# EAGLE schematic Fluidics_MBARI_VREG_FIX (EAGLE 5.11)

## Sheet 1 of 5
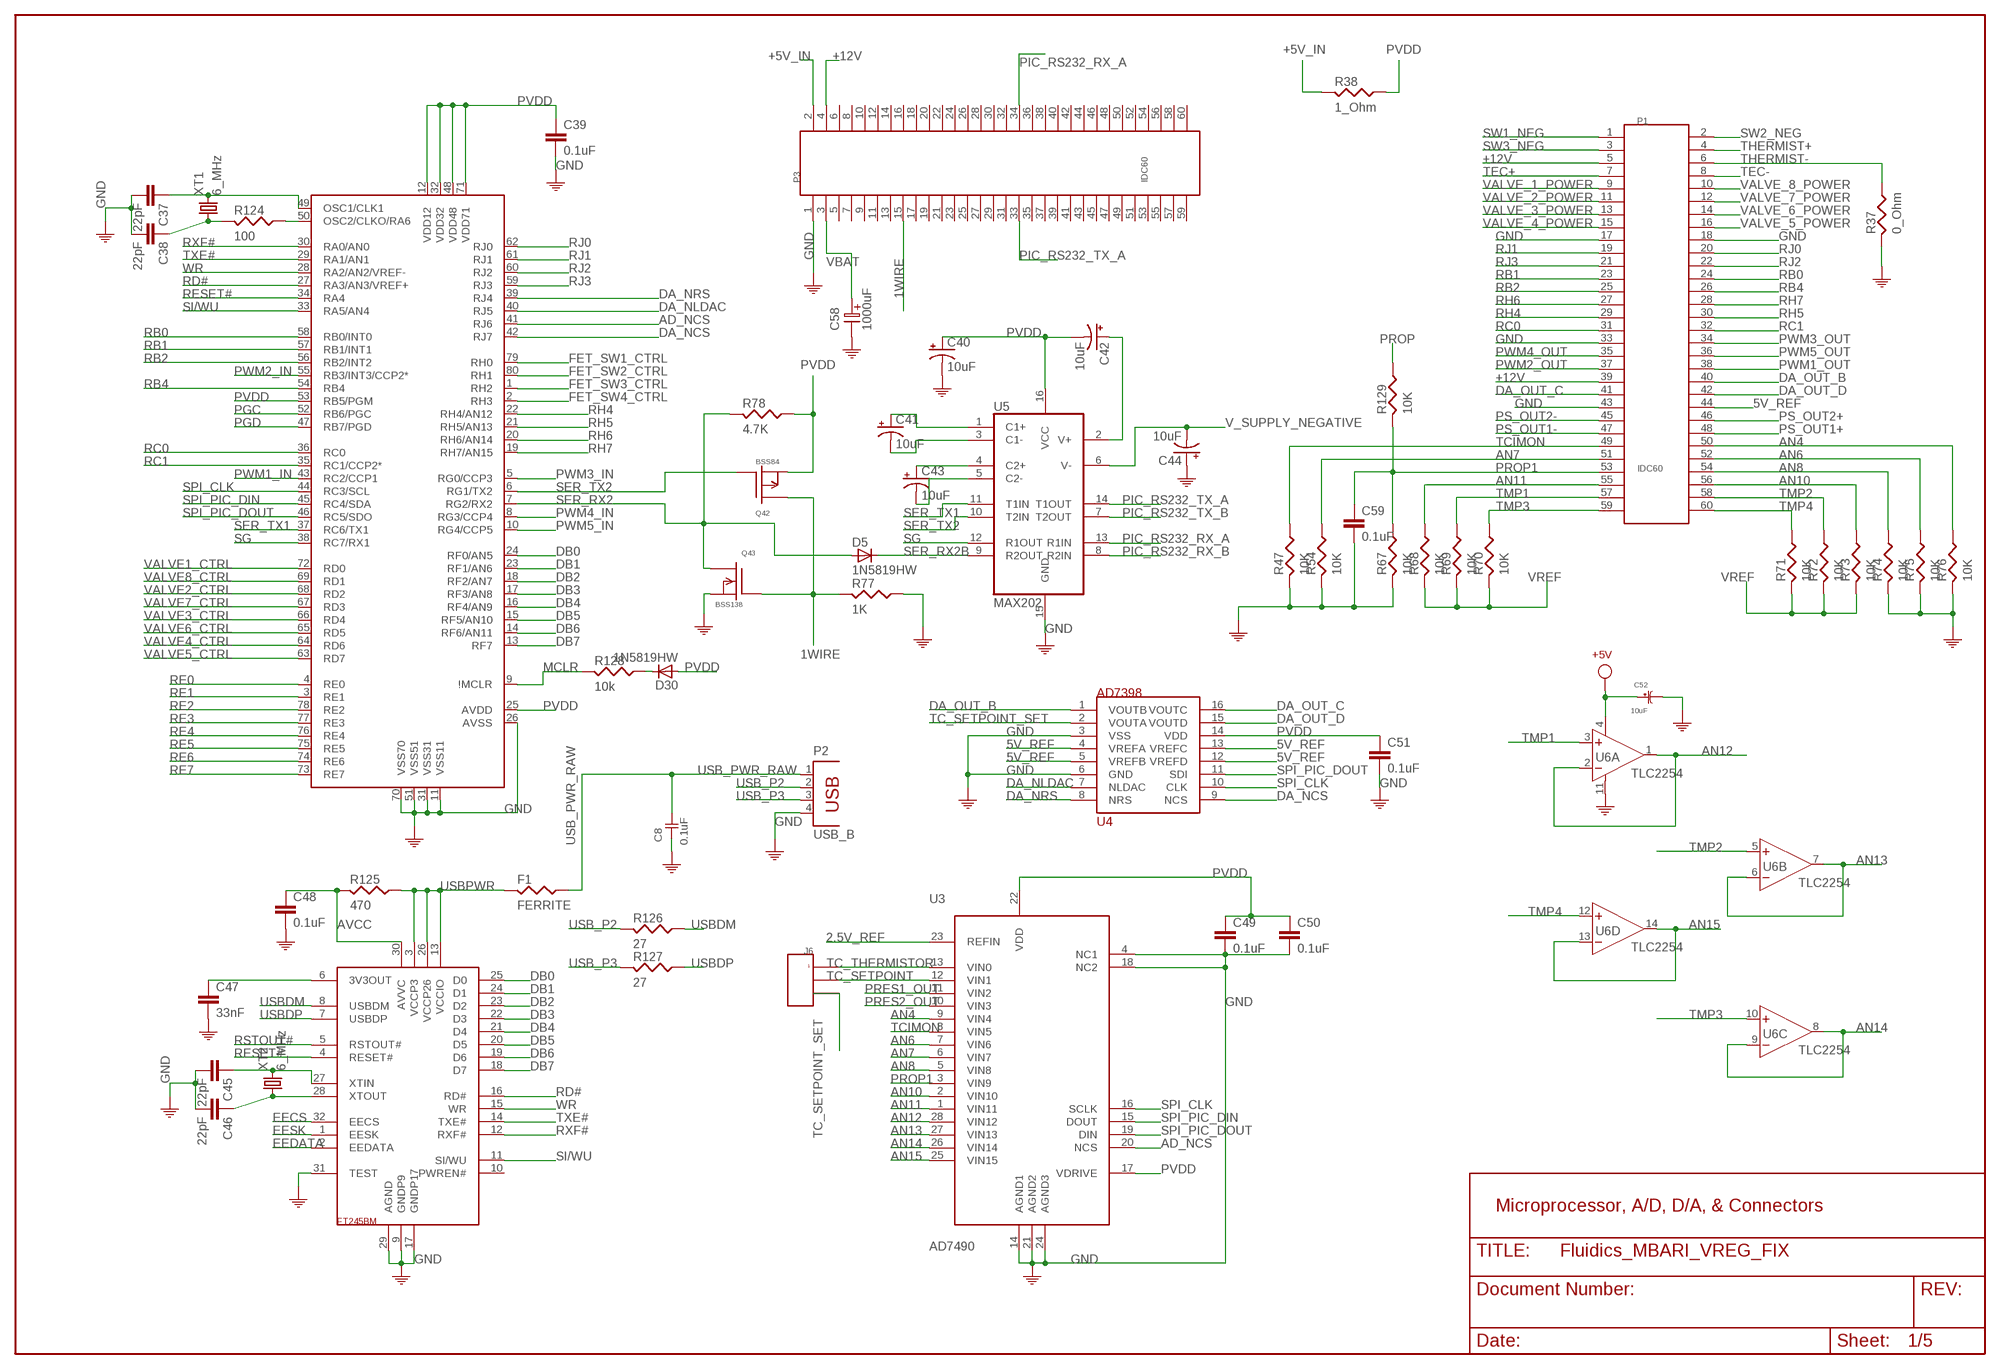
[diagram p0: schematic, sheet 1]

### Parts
C8  0.1uF  C0805  [0805]
C37  22pF  C-EUC0805  [C0805]
C38  22pF  C-EUC0805  [C0805]
C39  0.1uF  C-EUC0805  [C0805]
C40  10uF  CPOL-USCT3216  [CT3216]
C41  10uF  CPOL-USCT3216  [CT3216]
C42  10uF  CPOL-USCT3216  [CT3216]
C43  10uF  CPOL-USCT3216  [CT3216]
C44  10uF  CPOL-USCT3216  [CT3216]
C45  22pF  C-EUC0805  [C0805]
C46  22pF  C-EUC0805  [C0805]
C47  33nF  C-EUC0805  [C0805]
C48  0.1uF  C-EUC0805  [C0805]
C49  0.1uF  C-EUC0805  [C0805]
C50  0.1uF  C-EUC0805  [C0805]
C51  0.1uF  C-EUC0805  [C0805]
C52  10uF  POLCAP1210  [POLCAP1210]
C58  1000uF  ELC-5  [ES-5]
C59  0.1uF  C-EUC0805  [C0805]
D5  1N5819HW  D-SOD123  [SOD123]
D30  1N5819HW  D-SOD123  [SOD123]
F1  FERRITE  R0805  [0805]
J6  IDC3  [IDC3]
P1  IDC60  [IDC60]
P2  USB_B  PN61729  [PN61729]
P3  IDC60  [IDC60]
Q42  BSS84  MOSFETP  [SOT23]
Q43  BSS138  MOSFETN  [SOT23]
R37  0_Ohm  R0805  [0805]
R38  1_Ohm  R0805  [0805]
R47  10K  R0805  [0805]
R54  10K  R0805  [0805]
R67  10K  R0805  [0805]
R68  10K  R0805  [0805]
R69  10K  R0805  [0805]
R70  10K  R0805  [0805]
R71  10K  R0805  [0805]
R72  10K  R0805  [0805]
R73  10K  R0805  [0805]
R74  10K  R0805  [0805]
R75  10K  R0805  [0805]
R76  10K  R0805  [0805]
R77  1K  R0805  [0805]
R78  4.7K  R0805  [0805]
R124  100  R0805  [0805]
R125  470  R0805  [0805]
R126  27  R0805  [0805]
R127  27  R0805  [0805]
R128  10k  R0805  [0805]
R129  10K  R0805  [0805]
U1  PIC18F8720  PIC18F8720V1  [TQFP80]
U2  FT245BM  [LQFP-32]
U3  AD7490  [TSSOP28]
U4  AD7398  [TSSOP16]
U5  MAX202  [SO16]
U6  TLC2254  QUADOP  [SO-14]
XT1  6_MHz  CRYTALHC49S  [HC49/S]
XT2  6_MHz  CRYTALHC49S  [HC49/S]

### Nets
1WIRE: P3.15 Q42.3(D) Q43.1(G) R77.2
2.5V_REF: U3.23(REFIN) ; also sheet 4
5V_REF [+5V]: P1.44 U4.4(VREFA) U4.5(VREFB) U4.12(VREFD) U4.13(VREFC) ; also sheet 4
+5V: C52.2(+) U6.4(A:V+) ; also sheet 2,3
+5V_IN: P3.2 R38.2 ; also sheet 2,3,5
+12V: P1.5 P1.39 P3.4 ; also sheet 2,3,4,5
AD_NCS: U1.41(RJ6) U3.20(NCS)
AN4: P1.50 R76.1 U3.9(VIN4) ; also sheet 3
AN6: P1.52 R75.1 U3.7(VIN6)
AN7: P1.51 R54.1 U3.6(VIN7)
AN8: P1.54 R74.1 U3.5(VIN8) ; also sheet 3
AN10: P1.56 R73.1 U3.2(VIN10) ; also sheet 2
AN11: P1.55 R68.1 U3.1(VIN11) ; also sheet 2
AN12: U3.28(VIN12) U6.1(A:OUT) U6.2(A:-IN)
AN13: U3.27(VIN13) U6.6(B:-IN) U6.7(B:OUT)
AN14: U3.26(VIN14) U6.8(C:OUT) U6.9(C:-IN)
AN15: U3.25(VIN15) U6.13(D:-IN) U6.14(D:OUT)
AVCC: C48.1 R125.2 U2.30(AVVC)
DA_NCS: U1.42(RJ7) U4.9(NCS)
DA_NLDAC: U1.40(RJ5) U4.7(NLDAC)
DA_NRS: U1.39(RJ4) U4.8(NRS)
DA_OUT_B: P1.40 U4.1(VOUTB)
DA_OUT_C: P1.41 U4.16(VOUTC)
DA_OUT_D: P1.42 U4.15(VOUTD)
DB0: U1.24(RF0/AN5) U2.25(D0)
DB1: U1.23(RF1/AN6) U2.24(D1)
DB2: U1.18(RF2/AN7) U2.23(D2)
DB3: U1.17(RF3/AN8) U2.22(D3)
DB4: U1.16(RF4/AN9) U2.21(D4)
DB5: U1.15(RF5/AN10) U2.20(D5)
DB6: U1.14(RF6/AN11) U2.19(D6)
DB7: U1.13(RF7) U2.18(D7)
EECS: U2.32(EECS) ; also sheet 4
EEDATA: U2.2(EEDATA) ; also sheet 4
EESK: U2.1(EESK) ; also sheet 4
FET_SW1_CTRL: U1.79(RH0) ; also sheet 4
FET_SW2_CTRL: U1.80(RH1) ; also sheet 4
FET_SW3_CTRL: U1.1(RH2) ; also sheet 4
FET_SW4_CTRL: U1.2(RH3)
GND: C8.1 C37.2 C38.2 C39.2 C40.- C44.+ C45.2 C46.2 C47.2 C48.2 C49.2 C50.2 C51.2 C52.1(-) C58.2 C59.2 P1.17 P1.18 P1.33 P1.43 P2.4 P3.1 Q43.2(S) R37.2 R47.2 R54.2 R67.2 R74.2 R75.2 R76.2 R77.1 U1.11(VSS11) U1.26(AVSS) U1.31(VSS31) U1.51(VSS51) U1.70(VSS70) U2.9(GNDP9) U2.17(GNDP17) U2.29(AGND) U2.31(TEST) U3.4(NC1) U3.14(AGND1) U3.18(NC2) U3.21(AGND2) U3.24(AGND3) U4.3(VSS) U4.6(GND) U5.15(GND) U6.11(A:V-) ; also sheet 2,3,4,5
MCLR: R128.2 U1.9(\!MCLR) ; also sheet 4
N$1B: C37.1 U1.49(OSC1/CLK1) XT1.2
N$2B: C38.1 R124.2 XT1.1
N$3: R124.1 U1.50(OSC2/CLKO/RA6)
N$4B: C45.1 U2.27(XTIN) XT2.2
N$5B: C46.1 U2.28(XTOUT) XT2.1
N$92: D30.1(C) R128.1
N$93B: C47.1 U2.6(3V3OUT)
N$99B: C42.+ U5.2(V+)
N$101B: C41.+ U5.1(C1+)
N$102B: C41.- U5.3(C1-)
N$103B: C43.+ U5.4(C2+)
N$104B: C43.- U5.5(C2-)
PGC: U1.52(RB6/PGC) ; also sheet 4
PGD: U1.47(RB7/PGD) ; also sheet 4
PIC_RS232_RX_A: P3.34 U5.13(R1IN) ; also sheet 4
PIC_RS232_RX_B: U5.8(R2IN) ; also sheet 4
PIC_RS232_TX_A: P3.33 U5.14(T1OUT) ; also sheet 4
PIC_RS232_TX_B: U5.7(T2OUT) ; also sheet 4
PRES1_OUT: U3.11(VIN2) ; also sheet 4
PRES2_OUT: U3.10(VIN3) ; also sheet 4
PROP: R129.1 ; also sheet 2
PROP1: C59.1 P1.53 R67.1 R129.2 U3.3(VIN9)
PS_OUT1+: P1.48 ; also sheet 4
PS_OUT1-: P1.47 ; also sheet 4
PS_OUT2+: P1.46 ; also sheet 4
PS_OUT2-: P1.45 ; also sheet 4
PVDD: C39.1 C40.+ C42.- C49.1 C50.1 C51.1 D30.2(A) Q42.2(S) R38.1 R78.1 U1.12(VDD12) U1.25(AVDD) U1.32(VDD32) U1.48(VDD48) U1.53(RB5/PGM) U1.71(VDD71) U3.17(VDRIVE) U3.22(VDD) U4.14(VDD) U5.16(VCC) ; also sheet 4
PWM1_IN: U1.43(RC2/CCP1) ; also sheet 4
PWM1_OUT: P1.38 ; also sheet 4
PWM2_IN: U1.55(RB3/INT3/CCP2*) ; also sheet 4
PWM2_OUT: P1.37 ; also sheet 4
PWM3_IN: U1.5(RG0/CCP3) ; also sheet 4
PWM3_OUT: P1.34 ; also sheet 4
PWM4_IN: U1.8(RG3/CCP4) ; also sheet 4
PWM4_OUT: P1.35 ; also sheet 4
PWM5_IN: U1.10(RG4/CCP5) ; also sheet 4
PWM5_OUT: P1.36 ; also sheet 4
RB0: P1.24 U1.58(RB0/INT0)
RB1: P1.23 U1.57(RB1/INT1)
RB2: P1.25 U1.56(RB2/INT2)
RB4: P1.26 U1.54(RB4)
RC0: P1.31 U1.36(RC0)
RC1: P1.32 U1.35(RC1/CCP2*)
RD#: U1.27(RA3/AN3/VREF+) U2.16(RD#)
RE0: U1.4(RE0)
RE1: U1.3(RE1)
RE2: U1.78(RE2)
RE3: U1.77(RE3)
RE4: U1.76(RE4)
RE5: U1.75(RE5)
RE6: U1.74(RE6)
RE7: U1.73(RE7)
RESET#: U1.34(RA4) U2.4(RESET#)
RH4: P1.29 U1.22(RH4/AN12)
RH5: P1.30 U1.21(RH5/AN13)
RH6: P1.27 U1.20(RH6/AN14)
RH7: P1.28 U1.19(RH7/AN15)
RJ0: P1.20 U1.62(RJ0)
RJ1: P1.19 U1.61(RJ1)
RJ2: P1.22 U1.60(RJ2)
RJ3: P1.21 U1.59(RJ3)
RSTOUT#: U2.5(RSTOUT#) ; also sheet 4
RXF#: U1.30(RA0/AN0) U2.12(RXF#)
SER_RX2: D5.2(A) Q43.3(D) R78.2 U1.7(RG2/RX2)
SER_RX2B: D5.1(C) U5.9(R2OUT)
SER_TX1: U1.37(RC6/TX1) U5.11(T1IN)
SER_TX2: Q42.1(G) U1.6(RG1/TX2) U5.10(T2IN)
SG: U1.38(RC7/RX1) U5.12(R1OUT)
SI/WU: U1.33(RA5/AN4) U2.11(SI/WU)
SPI_CLK: U1.44(RC3/SCL) U3.16(SCLK) U4.10(CLK)
SPI_PIC_DIN: U1.45(RC4/SDA) U3.15(DOUT)
SPI_PIC_DOUT: U1.46(RC5/SDO) U3.19(DIN) U4.11(SDI)
SW1_NEG: P1.1 ; also sheet 4
SW2_NEG: P1.2 ; also sheet 4
SW3_NEG: P1.3 ; also sheet 4
TC_SETPOINT: J6.2 U3.12(VIN1)
TC_SETPOINT_SET: J6.3 U4.2(VOUTA) ; also sheet 2
TC_THERMISTOR: J6.1 U3.13(VIN0) ; also sheet 2
TCIMON: P1.49 R47.1 U3.8(VIN5) ; also sheet 2
TEC+: P1.7 ; also sheet 2
TEC-: P1.8 ; also sheet 2
THERMIST+: P1.4 ; also sheet 2
THERMIST-: P1.6 R37.1
TMP1: P1.57 R69.1 U6.3(A:+IN)
TMP2: P1.58 R72.1 U6.5(B:+IN)
TMP3: P1.59 R70.1 U6.10(C:+IN)
TMP4: P1.60 R71.1 U6.12(D:+IN)
TXE#: U1.29(RA1/AN1) U2.14(TXE#)
USB_P2: P2.2 R126.2
USB_P3: P2.3 R127.2
USB_PWR_RAW: C8.2 F1.1 P2.1
USBDM: R126.1 U2.8(USBDM)
USBDP: R127.1 U2.7(USBDP) ; also sheet 4
USBPWR: F1.2 R125.1 U2.3(VCCP3) U2.13(VCCIO) U2.26(VCCP26) ; also sheet 4
V_SUPPLY_NEGATIVE: C44.- U5.6(V-)
VALVE1_CTRL: U1.72(RD0) ; also sheet 5
VALVE2_CTRL: U1.68(RD2) ; also sheet 5
VALVE3_CTRL: U1.66(RD4) ; also sheet 5
VALVE4_CTRL: U1.64(RD6) ; also sheet 5
VALVE5_CTRL: U1.63(RD7) ; also sheet 5
VALVE6_CTRL: U1.65(RD5) ; also sheet 5
VALVE7_CTRL: U1.67(RD3) ; also sheet 5
VALVE8_CTRL: U1.69(RD1) ; also sheet 5
VALVE_1_POWER: P1.9 ; also sheet 5
VALVE_2_POWER: P1.11 ; also sheet 5
VALVE_3_POWER: P1.13 ; also sheet 5
VALVE_4_POWER: P1.15 ; also sheet 5
VALVE_5_POWER: P1.16 ; also sheet 5
VALVE_6_POWER: P1.14 ; also sheet 5
VALVE_7_POWER: P1.12 ; also sheet 5
VALVE_8_POWER: P1.10 ; also sheet 5
VBAT: C58.1 P3.3 ; also sheet 3
VREF: R68.2 R69.2 R70.2 R71.2 R72.2 R73.2 ; also sheet 2
WR: U1.28(RA2/AN2/VREF-) U2.15(WR)
Unconnected: P3.5 P3.6 P3.7 P3.8 P3.9 P3.10 P3.11 P3.12 P3.13 P3.14 P3.16 P3.17 P3.18 P3.19 P3.20 P3.21 P3.22 P3.23 P3.24 P3.25 P3.26 P3.27 P3.28 P3.29 P3.30 P3.31 P3.32 P3.35 P3.36 P3.37 P3.38 P3.39 P3.40 P3.41 P3.42 P3.43 P3.44 P3.45 P3.46 P3.47 P3.48 P3.49 P3.50 P3.51 P3.52 P3.53 P3.54 P3.55 P3.56 P3.57 P3.58 P3.59 P3.60 U2.10(PWREN#)

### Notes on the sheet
- Microprocessor, A/D, D/A, & Connectors

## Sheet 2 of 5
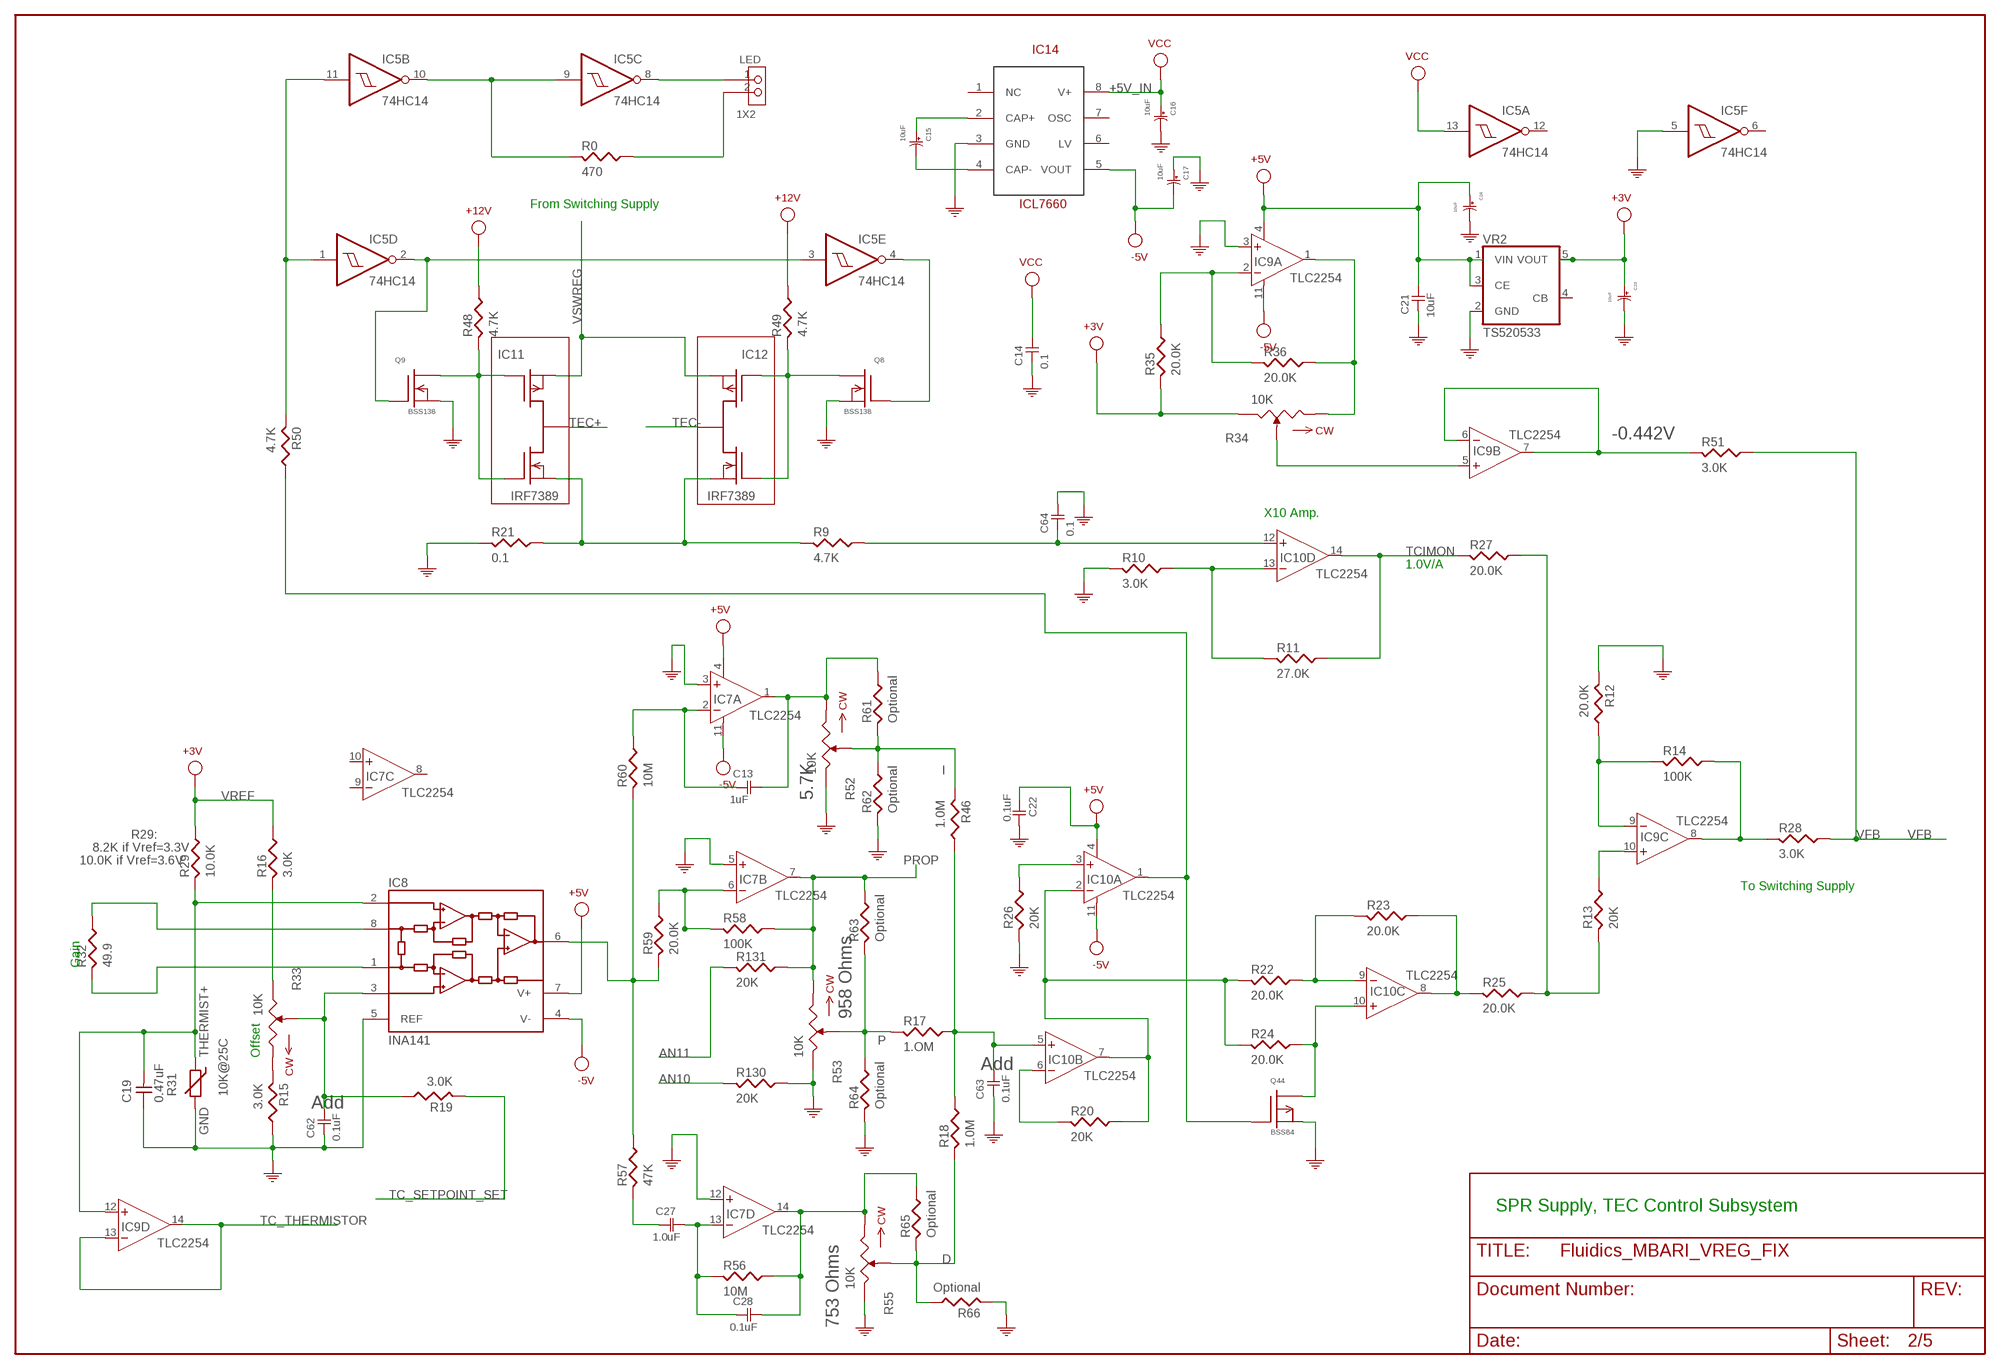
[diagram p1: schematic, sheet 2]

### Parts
C13  1uF  C-BIG  [C200]
C14  0.1  C0805  [0805]
C15  10uF  POLCAP1210  [POLCAP1210]
C16  10uF  POLCAP1210  [POLCAP1210]
C17  10uF  POLCAP1210  [POLCAP1210]
C19  0.47uF  CAPNP-5  [C-5]
C21  10uF  C0805  [0805]
C22  0.1uF  C0805  [0805]
C23  10uF  CPOL  [C100P]
C24  10uF  CPOL  [C100P]
C27  1.0uF  C-BIG  [C200]
C28  0.1uF  C0805  [0805]
C62  0.1uF  C0805  [0805]
C63  0.1uF  C0805  [0805]
C64  0.1  C0805  [0805]
IC5  74HC14  74LS14D  [SO14]
IC7  TLC2254  QUADOP  [SO-14]
IC8  INA141  [INA141SOIC]
IC9  TLC2254  QUADOP  [SO-14]
IC10  TLC2254  QUADOP  [SO-14]
IC11  IRF7389  DUALFET1  [DUALFET1]
IC12  IRF7389  DUALFET1  [DUALFET1]
IC14  ICL7660  [SO8]
LED  1X2  [1X2]
Q8  BSS138  MOSFETN  [SOT23]
Q9  BSS138  MOSFETN  [SOT23]
Q44  BSS84  MOSFETP  [SOT23]
R0  470  R0805  [0805]
R9  4.7K  R0805  [0805]
R10  3.0K  R0805  [0805]
R11  27.0K  R0805  [0805]
R12  20.0K  R0805  [0805]
R13  20K  R0805  [0805]
R14  100K  R0805  [0805]
R15  3.0K  R0805  [0805]
R16  3.0K  R0805  [0805]
R17  1.OM  R0805  [0805]
R18  1.0M  R0805  [0805]
R19  3.0K  R0805  [0805]
R20  20K  R0805  [0805]
R21  0.1  R-1/4W  [R-10]
R22  20.0K  R0805  [0805]
R23  20.0K  R0805  [0805]
R24  20.0K  R0805  [0805]
R25  20.0K  R0805  [0805]
R26  20K  R0805  [0805]
R27  20.0K  R0805  [0805]
R28  3.0K  R0805  [0805]
R29  10.0K  R0805  [0805]
R31  10K@25C  THERMISTOR-2,5  [RS-2,5]
R32  49.9  R0805  [0805]
R33  10K  TRIMPOT  [TRIMPOT1]
R34  10K  TRIMPOT  [TRIMPOT1]
R35  20.0K  R0805  [0805]
R36  20.0K  R0805  [0805]
R46  1.0M  R0805  [0805]
R48  4.7K  R0805  [0805]
R49  4.7K  R0805  [0805]
R50  4.7K  R0805  [0805]
R51  3.0K  R0805  [0805]
R52  10K  TRIMPOT  [TRIMPOT1]
R53  10K  TRIMPOT  [TRIMPOT1]
R55  10K  TRIMPOT  [TRIMPOT1]
R56  10M  R0805  [0805]
R57  47K  R0805  [0805]
R58  100K  R0805  [0805]
R59  20.0K  R0805  [0805]
R60  10M  R0805  [0805]
R61  Optional  R0805  [0805]
R62  Optional  R0805  [0805]
R63  Optional  R0805  [0805]
R64  Optional  R0805  [0805]
R65  Optional  R0805  [0805]
R66  Optional  R0805  [0805]
R130  20K  R0805  [0805]
R131  20K  R0805  [0805]
VR2  TS520533  [SOT25]

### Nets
+5V: C14.2 C21.2 C22.1 C24.+ IC5.13(A:I) IC7.4(A:V+) IC8.7(V+) IC9.4(A:V+) IC10.4(A:V+) VR2.1(VIN) VR2.3(CE) ; supply symbol labelled VCC ; also sheet 1,3
+5V_IN: C16.2(+) IC14.8(V+) ; supply symbol labelled VCC ; also sheet 1,3,5
+12V: R48.1 R49.1 ; also sheet 1,3,4,5
-5V_2: C17.1(-) IC7.11(A:V-) IC8.4(V-) IC9.11(A:V-) IC10.11(A:V-) IC14.5(VOUT) ; supply symbol labelled -5V ; also sheet 3,4
AN10: R130.2 ; also sheet 1
AN11: R131.2 ; also sheet 1
D: R18.2 R55.3 R65.2 R66.1
GND: C14.1 C16.1(-) C17.2(+) C19.1 C21.1 C22.2 C23.- C24.- C62.1 C63.1 C64.2 IC5.5(F:I) IC7.3(A:+IN) IC7.5(B:+IN) IC7.12(D:+IN) IC8.5(REF) IC9.3(A:+IN) IC14.3(GND) Q8.2(S) Q9.2(S) Q44.2(S) R10.2 R12.2 R15.1 R21.2 R26.2 R31.2 R52.1 R53.1 R55.1 R62.2 R64.2 R66.2 R130.1 VR2.2(GND) ; also sheet 1,3,4,5
I: R46.2 R52.3 R61.2 R62.1
N$18: IC10.13(D:-IN) R10.1 R11.2
N$21: IC10.6(B:-IN) R20.2
N$22: IC11.1(SN) IC12.1(SN) R9.2 R21.1
N$24: IC5.2(D:O) IC5.3(E:I) Q9.1(G)
N$25: IC5.4(E:O) Q8.1(G)
N$26: R13.2 R25.1 R27.1
N$27: IC9.6(B:-IN) IC9.7(B:OUT) R51.2
N$28: IC10.1(A:OUT) Q44.1(G) R50.1
N$29: IC10.9(C:-IN) R22.1 R23.2
N$30: IC10.8(C:OUT) R23.1 R25.2
N$32: IC10.10(C:+IN) Q44.3(D) R24.1
N$33: IC9.5(B:+IN) R34.3
N$34: C63.2 IC10.5(B:+IN) R17.1 R18.1 R46.1
N$37: IC8.1(J) R32.2
N$39: R15.2 R33.2
N$40: R16.2 R33.1
N$42: IC9.10(C:+IN) R13.1
N$43: IC10.3(A:+IN) R26.1
N$44: C64.1 IC10.12(D:+IN) R9.1
N$45: IC9.8(C:OUT) R14.1 R28.2
N$46: C15.2(+) IC14.2(CAP+)
N$47: IC5.9(C:I) IC5.10(B:O) R0.2
N$48: IC9.2(A:-IN) R35.1 R36.2
N$49: IC5.8(C:O) LED.1
N$50: C15.1(-) IC14.4(CAP-)
N$52: IC9.9(C:-IN) R12.1 R14.2
N$61: LED.2 R0.1
N$63: IC12.2(GN) IC12.4(GP) Q8.3(D) R49.2
N$64: IC11.2(GN) IC11.4(GP) Q9.3(D) R48.2
N$66: C13.2 IC7.1(A:OUT) R52.2 R61.1
N$68: C13.1 IC7.2(A:-IN) R60.1
N$70: IC5.1(D:I) IC5.11(B:I) R50.2
N$71: IC8.6(OUT) R57.1 R59.2 R60.2
N$72: C28.2 IC7.14(D:OUT) R55.2 R56.1 R65.1
N$73: C27.2 C28.1 IC7.13(D:-IN) R56.2
N$74: C27.1 R57.2
N$75: IC7.6(B:-IN) R58.2 R59.1
P: R17.2 R53.3 R63.2 R64.1
PID_OUT: IC10.2(A:-IN) IC10.7(B:OUT) R20.1 R22.2 R24.2
PROP: IC7.7(B:OUT) R53.2 R58.1 R63.1 R131.1 ; also sheet 1
TC_SETPOINT_SET: R19.2 ; also sheet 1
TC_THERMISTOR: IC9.13(D:-IN) IC9.14(D:OUT) ; also sheet 1
TCIMON: IC10.14(D:OUT) R11.1 R27.2 ; also sheet 1
TEC+: IC11.5(D_NP) ; also sheet 1
TEC-: IC12.5(D_NP) ; also sheet 1
THERMIST+: C19.2 IC8.2(-IN) IC9.12(D:+IN) R29.2 R31.1 ; also sheet 1
TSET: C62.2 IC8.3(+IN) R19.1 R33.3
U5: IC8.8(J) R32.1
VFB: R28.1 R51.1 ; also sheet 3
VREF: C23.+ R16.1 R29.1 R34.1 R35.2 VR2.5(VOUT) ; also sheet 1
VREF-: IC9.1(A:OUT) R34.2 R36.1
VSWREG: IC11.3(SP) IC12.3(SP) ; also sheet 3
Unconnected: IC5.6(F:O) IC5.12(A:O) IC7.8(C:OUT) IC7.9(C:-IN) IC7.10(C:+IN) IC14.6(LV) IC14.7(OSC) VR2.4(CB)

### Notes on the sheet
- IC14
- From Switching Supply | ICL7660
- -0.442V
- X10 Amp.
- 1.0V/A
- 5.7K
- R29:
- 8.2K if Vref=3.3V
- 10.0K if Vref=3.6V
- To Switching Supply
- Gain
- 958 Ohms
- Offset
- Add
- Add
- SPR Supply, TEC Control Subsystem
- 753 Ohms

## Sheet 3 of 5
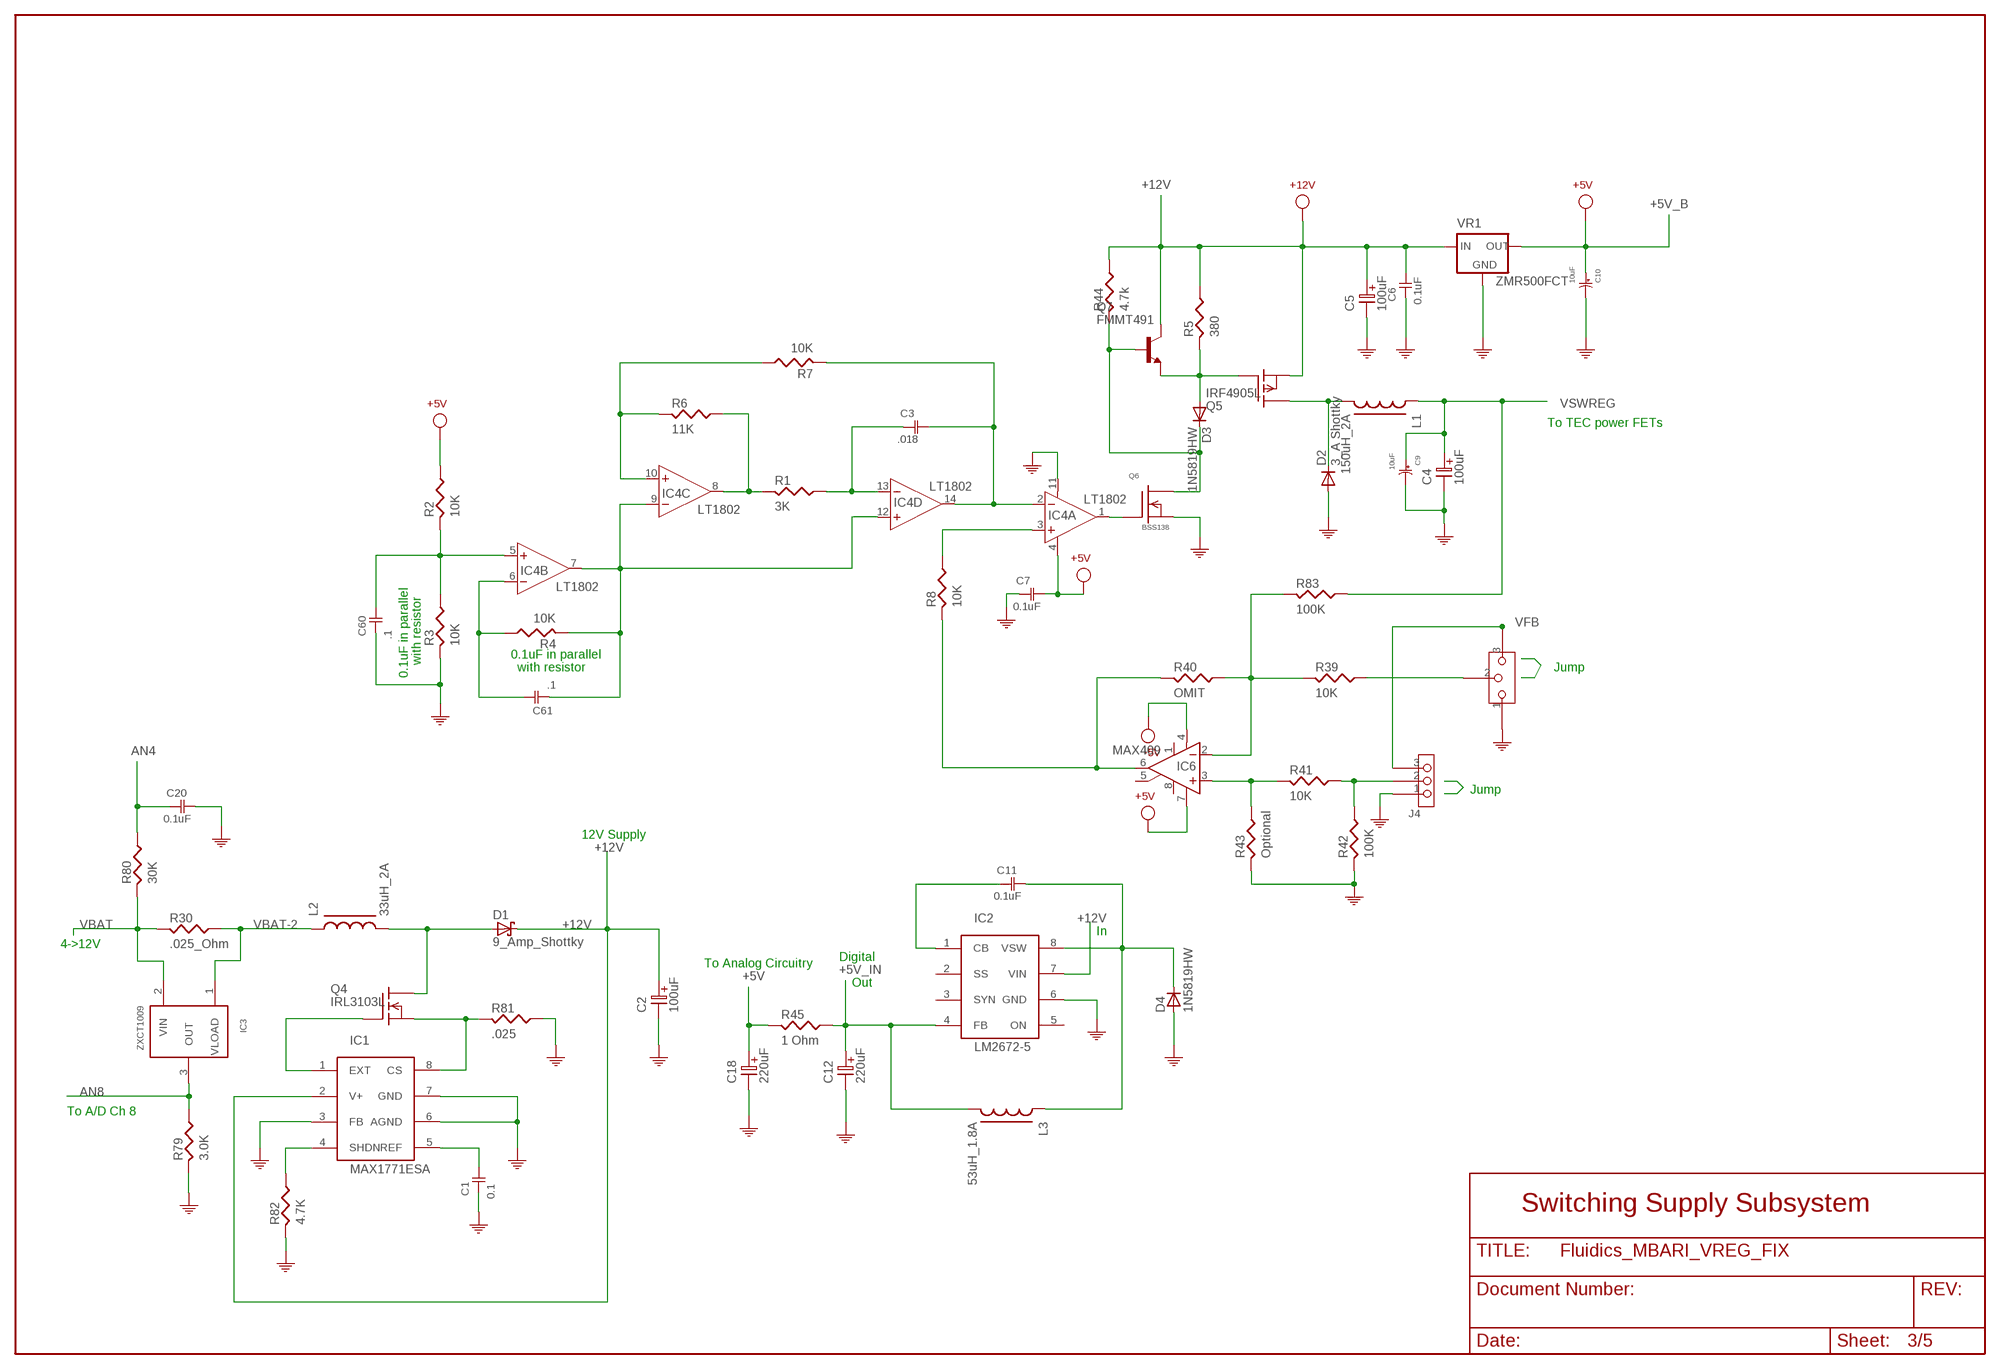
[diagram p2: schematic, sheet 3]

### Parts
C1  0.1  C0805  [0805]
C2  100uF  ELC-5  [ES-5]
C3  .018  C0805  [0805]
C4  100uF  ELC-5  [ES-5]
C5  100uF  ELC-5  [ES-5]
C6  0.1uF  C0805  [0805]
C7  0.1uF  C0805  [0805]
C9  10uF  POLCAP1210  [POLCAP1210]
C10  10uF  POLCAP1210  [POLCAP1210]
C11  0.1uF  C0805  [0805]
C12  220uF  ELC-5  [ES-5]
C18  220uF  ELC-5  [ES-5]
C20  0.1uF  C0805  [0805]
C60  .1  C0805  [0805]
C61  .1  C0805  [0805]
D1  9_Amp_Shottky  1N5908  [C4111-15]
D2  3_A Shottky  DIODE-SMC  [SMC]
D3  1N5819HW  ES2D  [SMB]
D4  1N5819HW  D-SOD123  [SOD123]
IC1  MAX1771ESA  MAX1771  [SO8]
IC2  LM2672-5  LM2672  [DIL8]
IC3  ZXCT1009  [SOT23]
IC4  LT1802  QUADOP  [SO-14]
IC6  MAX409  OPAMPSMD  [SO-8]
J2  JUMP3  [JUMP3]
J4  1X3  [1X3]
L1  150uH_2A  INDUCTOR1  [INDUCTOR1]
L2  33uH_2A  INDUCTOR2  [INDUCTOR2]
L3  53uH_1.8A  INDUCTOR1  [INDUCTOR1]
Q4  IRL3103L  IRF540  [TO220]
Q5  IRF4905L  IRF9530  [TO220]
Q6  BSS138  MOSFETN  [SOT23]
Q7  FMMT491  BCX20SMD  [SOT23-BEC]
R1  3K  R0805  [0805]
R2  10K  R0805  [0805]
R3  10K  R0805  [0805]
R4  10K  R0805  [0805]
R5  380  R0805  [0805]
R6  11K  R0805  [0805]
R7  10K  R0805  [0805]
R8  10K  R0805  [0805]
R30  .025_Ohm  R-1/4W  [R-10]
R39  10K  R0805  [0805]
R40  OMIT  R0805  [0805]
R41  10K  R0805  [0805]
R42  100K  R0805  [0805]
R43  Optional  R0805  [0805]
R44  4.7k  R0805  [0805]
R45  1 Ohm  R-1/4W  [R-10]
R79  3.0K  R0805  [0805]
R80  30K  R0805  [0805]
R81  .025  R-1/4W  [R-10]
R82  4.7K  R0805  [0805]
R83  100K  R0805  [0805]
VR1  ZMR500FCT  TOKO_SOT23  [SOT23]

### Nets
+5V: C18.1 IC6.7(V+) R45.2 ; also sheet 1,2
+5V_B: C7.2 C10.2(+) IC4.4(A:V+) R2.1 VR1.1(OUT) ; supply symbol labelled +5V
+5V_IN: C12.1 IC2.4(FB) L3.P$2 R45.1 ; also sheet 1,2,5
+12V: C2.1 C5.1 C6.2 D1.C IC1.2(V+) IC2.7(VIN) Q5.3(S) Q7.C R5.1 R44.1 VR1.2(IN) ; also sheet 1,2,4,5
-5V_2: IC6.4(V-) ; supply symbol labelled -5V ; also sheet 2,4
AN4: C20.1 R80.1 ; also sheet 1
AN8: IC3.3(OUT) R79.1 ; also sheet 1
GND: C1.1 C2.2 C4.2 C5.2 C6.1 C7.1 C9.1(-) C10.1(-) C12.2 C18.2 C20.2 C60.1 D2.A D4.2(A) IC1.3(FB) IC1.6(AGND) IC1.7(GND) IC2.6(GND) IC4.11(A:V-) J2.1 J4.1 Q6.2(S) R3.2 R42.2 R43.2 R79.2 R81.1 R82.2 VR1.3(GND) ; also sheet 1,2,4,5
N$23: D1.A L2.P$2 Q4.2(D)
N$35: IC1.1(EXT) Q4.1(G)
N$36: IC4.8(C:OUT) R1.2 R6.1
N$56: IC1.8(CS) Q4.3(S) R81.2
N$57: C11.2 D4.1(C) IC2.8(VSW) L3.P$1
N$58: C3.1 IC4.13(D:-IN) R1.1
N$59: C1.2 IC1.5(REF)
N$60: IC1.4(SHDN) R82.1
N$62: C11.1 IC2.1(CB)
N$122: C3.2 IC4.2(A:-IN) IC4.14(D:OUT) R7.2
N$132: C61.1 IC4.7(B:OUT) IC4.9(C:-IN) IC4.12(D:+IN) R4.2
N$133: IC4.1(A:OUT) Q6.1(G)
N$134: D2.C L1.P$2 Q5.2(D)
N$135: C60.2 IC4.5(B:+IN) R2.2 R3.1
N$136: C61.2 IC4.6(B:-IN) R4.1
N$137: IC4.10(C:+IN) R6.2 R7.1
N$138: IC4.3(A:+IN) R8.1
N$143: J2.2 R39.1
N$144: IC6.2(-IN) R39.2 R40.1 R83.2
N$145: IC6.3(+IN) R41.2 R43.1
N$146: J4.2 R41.1 R42.1
N$147: D3.A Q5.1(G) Q7.E R5.2
N$148: D3.C Q6.3(D) Q7.B R44.2
VBAT: IC3.2(VIN) R30.2 R80.2 ; also sheet 1
VBAT-2: IC3.1(VLOAD) L2.P$1 R30.1
VCONT: IC6.6(OUT) R8.2 R40.2
VFB: J2.3 J4.3 ; also sheet 2
VSWREG: C4.1 C9.2(+) L1.P$1 R83.1 ; also sheet 2
Unconnected: IC2.2(SS) IC2.3(SYN) IC2.5(ON) IC6.1(PIN1) IC6.5(PIN5) IC6.8(PIN8)

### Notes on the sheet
- To TEC power FETs
- 0.1uF in parallel
- with resistor
- with resistor | Jump
- 0.1uF in parallel
- Jump
- 12V Supply
- In
- 4->12V
- Digital
- To Analog Circuitry
- Out
- To A/D Ch 8
- Switching Supply Subsystem

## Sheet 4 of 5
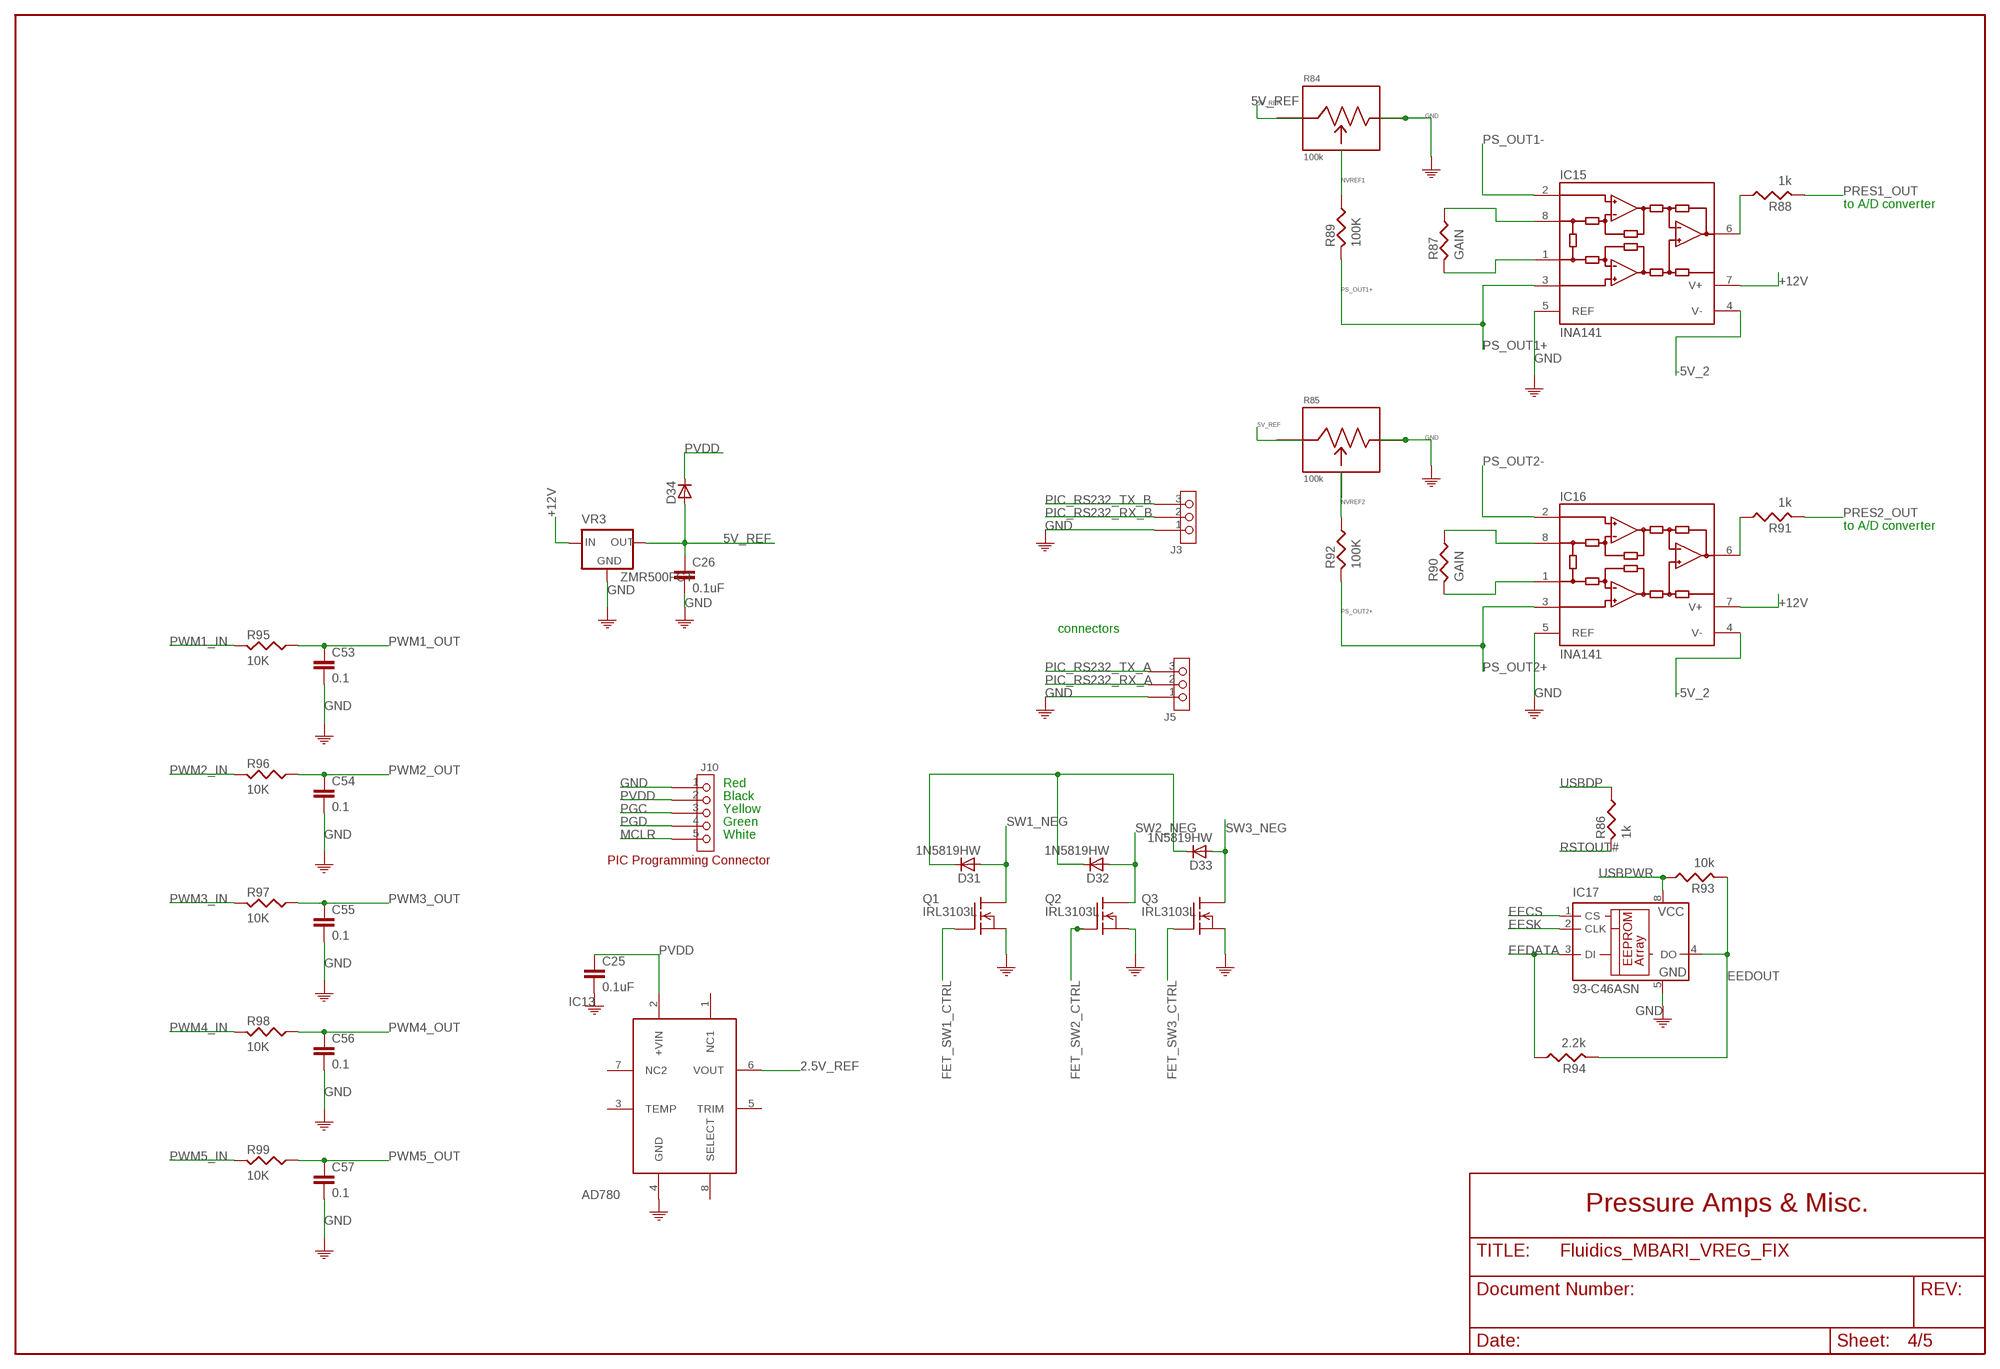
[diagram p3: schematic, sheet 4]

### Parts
C25  0.1uF  C-EUC0805  [C0805]
C26  0.1uF  C-EUC0805  [C0805]
C53  0.1  C-EUC0805  [C0805]
C54  0.1  C-EUC0805  [C0805]
C55  0.1  C-EUC0805  [C0805]
C56  0.1  C-EUC0805  [C0805]
C57  0.1  C-EUC0805  [C0805]
D31  1N5819HW  D-SOD123  [SOD123]
D32  1N5819HW  D-SOD123  [SOD123]
D33  1N5819HW  D-SOD123  [SOD123]
D34  D-SOD123  [SOD123]
IC13  AD780  [SO8]
IC15  INA141  [INA141SOIC]
IC16  INA141  [INA141SOIC]
IC17  93-C46ASN  [SO-08]
J3  1X3  [1X3]
J5  1X3  [1X3]
J10  1X5  [1X5]
Q1  IRL3103L  IRF540  [TO220]
Q2  IRL3103L  IRF540  [TO220]
Q3  IRL3103L  IRF540  [TO220]
R84  100k  POT  [POT]
R85  100k  POT  [POT]
R86  1k  R0805  [0805]
R87  GAIN  R0805  [0805]
R88  1k  R0805  [0805]
R89  100K  R0805  [0805]
R90  GAIN  R0805  [0805]
R91  1k  R0805  [0805]
R92  100K  R0805  [0805]
R93  10k  R0805  [0805]
R94  2.2k  R0805  [0805]
R95  10K  R0805  [0805]
R96  10K  R0805  [0805]
R97  10K  R0805  [0805]
R98  10K  R0805  [0805]
R99  10K  R0805  [0805]
VR3  ZMR500FCT  TOKO_SOT23  [SOT23]

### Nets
2.5V_REF: IC13.6(VOUT) ; also sheet 1
5V_REF [+5V]: C26.1 D34.2(A) R84.P$1 R85.P$1 VR3.1(OUT) ; also sheet 1
+12V: D31.1(C) D32.1(C) D33.1(C) IC15.7(V+) IC16.7(V+) VR3.2(IN) ; also sheet 1,2,3,5
-5V_2: IC15.4(V-) IC16.4(V-) ; also sheet 2,3
EECS: IC17.1(CS) ; also sheet 1
EEDATA: IC17.3(DI) R94.1 ; also sheet 1
EEDOUT: IC17.4(DO) R93.2 R94.2
EESK: IC17.2(CLK) ; also sheet 1
FET_SW1_CTRL: Q1.1(G) ; also sheet 1
FET_SW2_CTRL: Q2.1(G) ; also sheet 1
FET_SW3_CTRL: Q3.1(G) ; also sheet 1
GND: C25.2 C26.2 C53.2 C54.2 C55.2 C56.2 C57.2 IC13.4(GND) IC15.5(REF) IC16.5(REF) IC17.5(GND) J3.1 J5.1 J10.1 Q1.3(S) Q2.3(S) Q3.3(S) R84.P$3 R85.P$3 VR3.3(GND) ; also sheet 1,2,3,5
IC14: IC16.1(J) R90.2
IC15: IC15.8(J) R87.1
MCLR: J10.5 ; also sheet 1
N$95: IC16.8(J) R90.1
N$98: IC16.6(OUT) R91.1
N$106: IC15.1(J) R87.2
N$107: IC15.6(OUT) R88.1
NVREF1: R84.P$2 R89.1
NVREF2: R85.P$2 R92.1
PGC: J10.3 ; also sheet 1
PGD: J10.4 ; also sheet 1
PIC_RS232_RX_A: J5.2 ; also sheet 1
PIC_RS232_RX_B: J3.2 ; also sheet 1
PIC_RS232_TX_A: J5.3 ; also sheet 1
PIC_RS232_TX_B: J3.3 ; also sheet 1
PRES1_OUT: R88.2 ; also sheet 1
PRES2_OUT: R91.2 ; also sheet 1
PS_OUT1+: IC15.3(+IN) R89.2 ; also sheet 1
PS_OUT1-: IC15.2(-IN) ; also sheet 1
PS_OUT2+: IC16.3(+IN) R92.2 ; also sheet 1
PS_OUT2-: IC16.2(-IN) ; also sheet 1
PVDD: C25.1 D34.1(C) IC13.2(+VIN) J10.2 ; also sheet 1
PWM1_IN: R95.2 ; also sheet 1
PWM1_OUT: C53.1 R95.1 ; also sheet 1
PWM2_IN: R96.2 ; also sheet 1
PWM2_OUT: C54.1 R96.1 ; also sheet 1
PWM3_IN: R97.2 ; also sheet 1
PWM3_OUT: C55.1 R97.1 ; also sheet 1
PWM4_IN: R98.2 ; also sheet 1
PWM4_OUT: C56.1 R98.1 ; also sheet 1
PWM5_IN: R99.2 ; also sheet 1
PWM5_OUT: C57.1 R99.1 ; also sheet 1
RSTOUT#: R86.2 ; also sheet 1
SW1_NEG: D31.2(A) Q1.2(D) ; also sheet 1
SW2_NEG: D32.2(A) Q2.2(D) ; also sheet 1
SW3_NEG: D33.2(A) Q3.2(D) ; also sheet 1
USBDP: R86.1 ; also sheet 1
USBPWR: IC17.8(VCC) R93.1 ; also sheet 1
Unconnected: IC13.1(NC1) IC13.3(TEMP) IC13.5(TRIM) IC13.7(NC2) IC13.8(SELECT)

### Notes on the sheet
- to A/D converter
- to A/D converter
- connectors
- Red
- Black
- Yellow
- Green
- White
- PIC Programming Connector
- Pressure Amps & Misc.

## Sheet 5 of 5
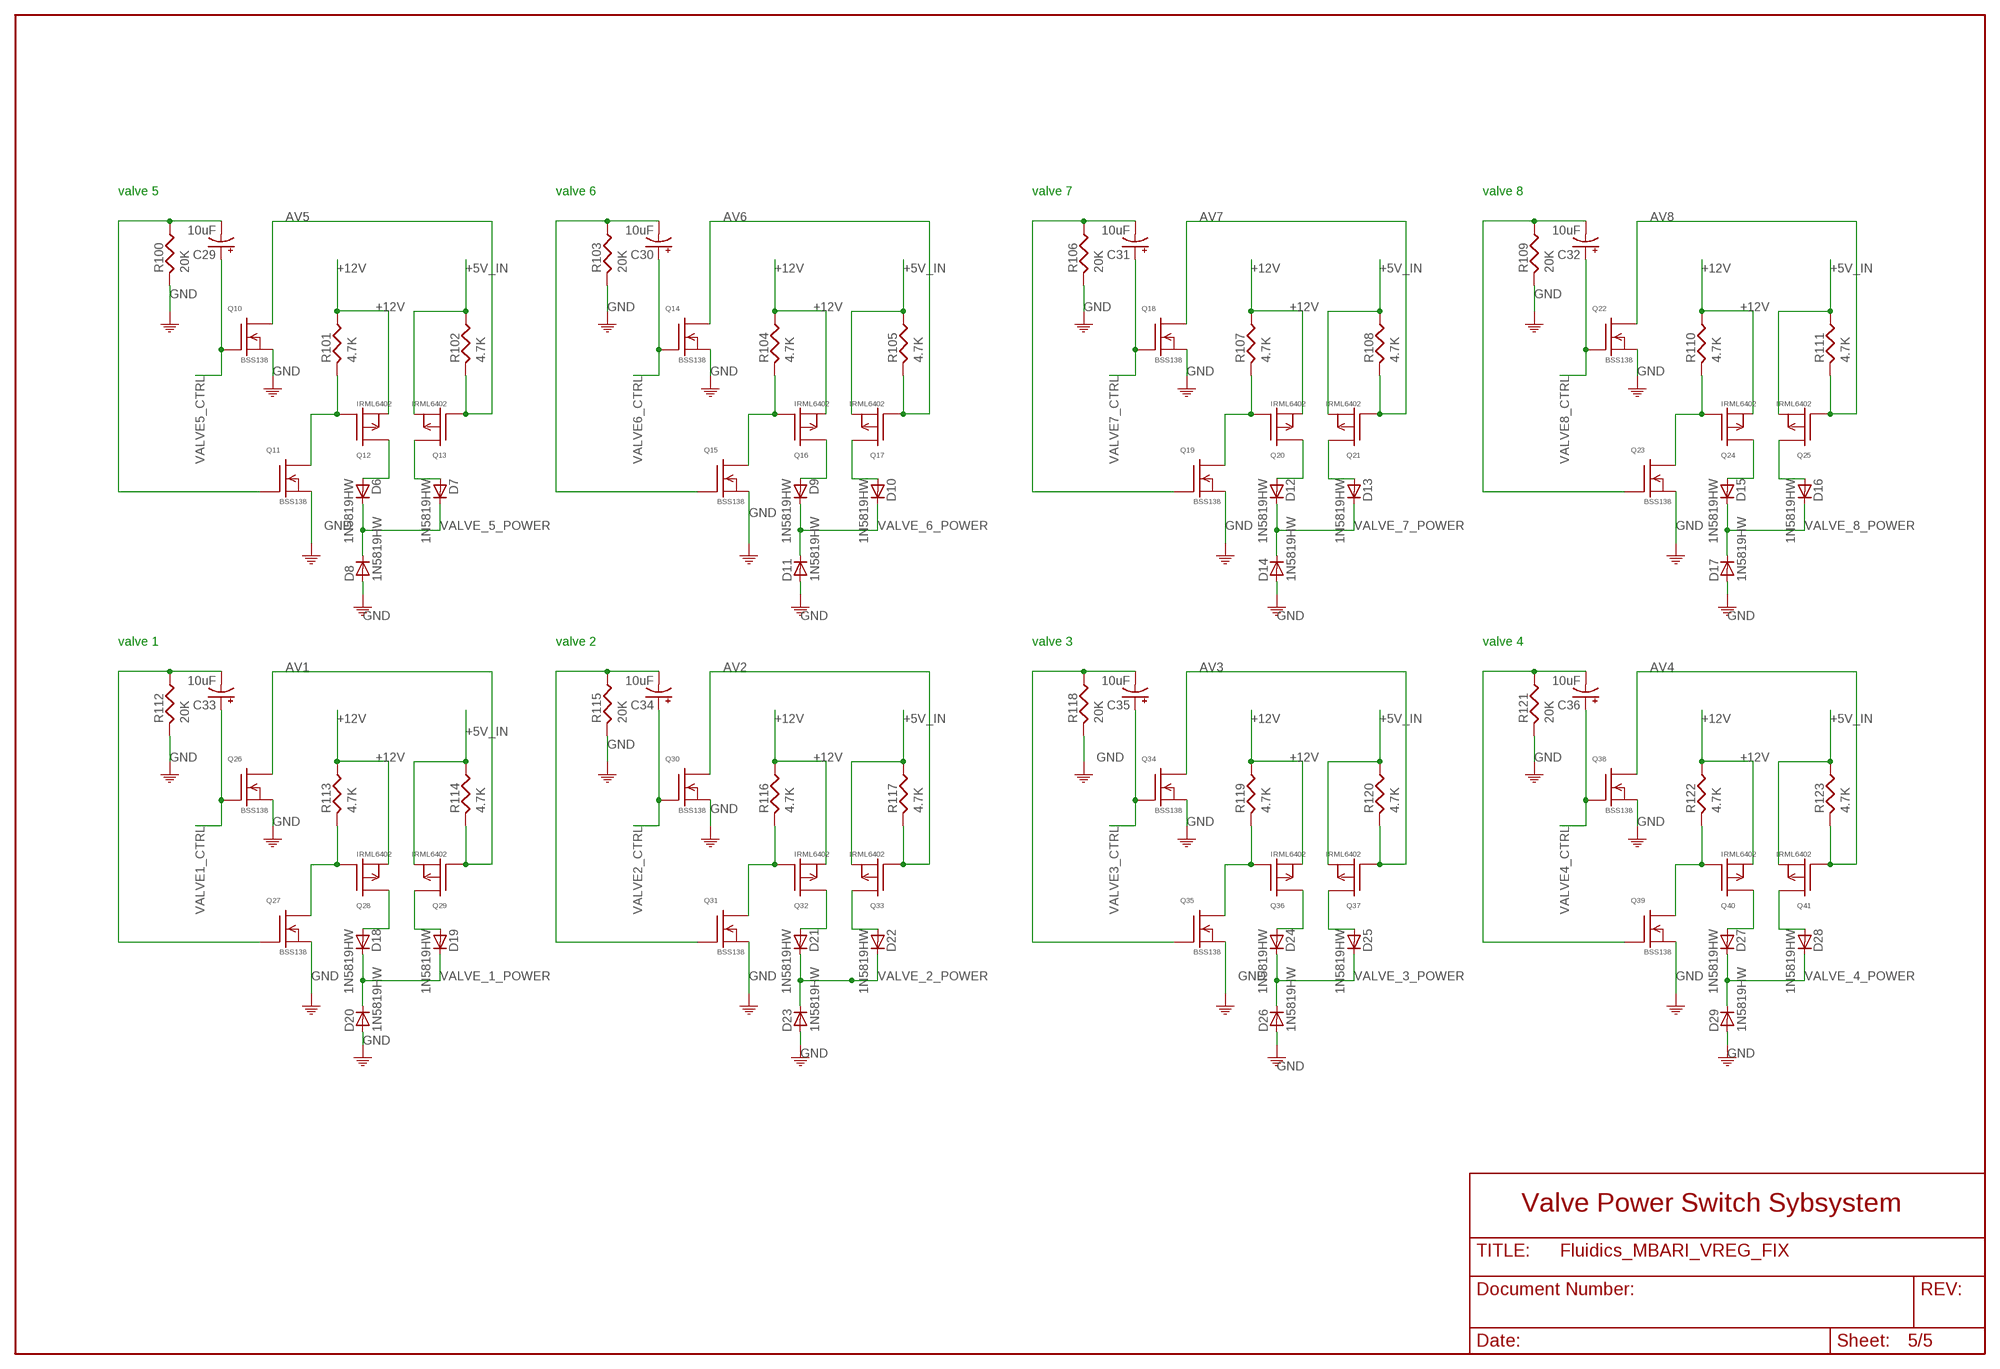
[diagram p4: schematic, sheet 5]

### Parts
C29  10uF  CPOL-USCT3216  [CT3216]
C30  10uF  CPOL-USCT3216  [CT3216]
C31  10uF  CPOL-USCT3216  [CT3216]
C32  10uF  CPOL-USCT3216  [CT3216]
C33  10uF  CPOL-USCT3216  [CT3216]
C34  10uF  CPOL-USCT3216  [CT3216]
C35  10uF  CPOL-USCT3216  [CT3216]
C36  10uF  CPOL-USCT3216  [CT3216]
D6  1N5819HW  D-SOD123  [SOD123]
D7  1N5819HW  D-SOD123  [SOD123]
D8  1N5819HW  D-SOD123  [SOD123]
D9  1N5819HW  D-SOD123  [SOD123]
D10  1N5819HW  D-SOD123  [SOD123]
D11  1N5819HW  D-SOD123  [SOD123]
D12  1N5819HW  D-SOD123  [SOD123]
D13  1N5819HW  D-SOD123  [SOD123]
D14  1N5819HW  D-SOD123  [SOD123]
D15  1N5819HW  D-SOD123  [SOD123]
D16  1N5819HW  D-SOD123  [SOD123]
D17  1N5819HW  D-SOD123  [SOD123]
D18  1N5819HW  D-SOD123  [SOD123]
D19  1N5819HW  D-SOD123  [SOD123]
D20  1N5819HW  D-SOD123  [SOD123]
D21  1N5819HW  D-SOD123  [SOD123]
D22  1N5819HW  D-SOD123  [SOD123]
D23  1N5819HW  D-SOD123  [SOD123]
D24  1N5819HW  D-SOD123  [SOD123]
D25  1N5819HW  D-SOD123  [SOD123]
D26  1N5819HW  D-SOD123  [SOD123]
D27  1N5819HW  D-SOD123  [SOD123]
D28  1N5819HW  D-SOD123  [SOD123]
D29  1N5819HW  D-SOD123  [SOD123]
Q10  BSS138  MOSFETN  [SOT23]
Q11  BSS138  MOSFETN  [SOT23]
Q12  IRML6402  MOSFETP  [SOT23]
Q13  IRML6402  MOSFETP  [SOT23]
Q14  BSS138  MOSFETN  [SOT23]
Q15  BSS138  MOSFETN  [SOT23]
Q16  IRML6402  MOSFETP  [SOT23]
Q17  IRML6402  MOSFETP  [SOT23]
Q18  BSS138  MOSFETN  [SOT23]
Q19  BSS138  MOSFETN  [SOT23]
Q20  IRML6402  MOSFETP  [SOT23]
Q21  IRML6402  MOSFETP  [SOT23]
Q22  BSS138  MOSFETN  [SOT23]
Q23  BSS138  MOSFETN  [SOT23]
Q24  IRML6402  MOSFETP  [SOT23]
Q25  IRML6402  MOSFETP  [SOT23]
Q26  BSS138  MOSFETN  [SOT23]
Q27  BSS138  MOSFETN  [SOT23]
Q28  IRML6402  MOSFETP  [SOT23]
Q29  IRML6402  MOSFETP  [SOT23]
Q30  BSS138  MOSFETN  [SOT23]
Q31  BSS138  MOSFETN  [SOT23]
Q32  IRML6402  MOSFETP  [SOT23]
Q33  IRML6402  MOSFETP  [SOT23]
Q34  BSS138  MOSFETN  [SOT23]
Q35  BSS138  MOSFETN  [SOT23]
Q36  IRML6402  MOSFETP  [SOT23]
Q37  IRML6402  MOSFETP  [SOT23]
Q38  BSS138  MOSFETN  [SOT23]
Q39  BSS138  MOSFETN  [SOT23]
Q40  IRML6402  MOSFETP  [SOT23]
Q41  IRML6402  MOSFETP  [SOT23]
R100  20K  R0805  [0805]
R101  4.7K  R0805  [0805]
R102  4.7K  R0805  [0805]
R103  20K  R0805  [0805]
R104  4.7K  R0805  [0805]
R105  4.7K  R0805  [0805]
R106  20K  R0805  [0805]
R107  4.7K  R0805  [0805]
R108  4.7K  R0805  [0805]
R109  20K  R0805  [0805]
R110  4.7K  R0805  [0805]
R111  4.7K  R0805  [0805]
R112  20K  R0805  [0805]
R113  4.7K  R0805  [0805]
R114  4.7K  R0805  [0805]
R115  20K  R0805  [0805]
R116  4.7K  R0805  [0805]
R117  4.7K  R0805  [0805]
R118  20K  R0805  [0805]
R119  4.7K  R0805  [0805]
R120  4.7K  R0805  [0805]
R121  20K  R0805  [0805]
R122  4.7K  R0805  [0805]
R123  4.7K  R0805  [0805]

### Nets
+5V_IN: Q13.2(S) Q17.2(S) Q21.2(S) Q25.2(S) Q29.2(S) Q33.2(S) Q37.2(S) Q41.2(S) R102.1 R105.1 R108.1 R111.1 R114.1 R117.1 R120.1 R123.1 ; also sheet 1,2,3
+12V: Q12.2(S) Q16.2(S) Q20.2(S) Q24.2(S) Q28.2(S) Q32.2(S) Q36.2(S) Q40.2(S) R101.1 R104.1 R107.1 R110.1 R113.1 R116.1 R119.1 R122.1 ; also sheet 1,2,3,4
AV1: Q26.3(D) Q29.1(G) R114.2
AV2: Q30.3(D) Q33.1(G) R117.2
AV3: Q34.3(D) Q37.1(G) R120.2
AV4: Q38.3(D) Q41.1(G) R123.2
AV5: Q10.3(D) Q13.1(G) R102.2
AV6: Q14.3(D) Q17.1(G) R105.2
AV7: Q18.3(D) Q21.1(G) R108.2
AV8: Q22.3(D) Q25.1(G) R111.2
GND: D8.2(A) D11.2(A) D14.2(A) D17.2(A) D20.2(A) D23.2(A) D26.2(A) D29.2(A) Q10.2(S) Q11.2(S) Q14.2(S) Q15.2(S) Q18.2(S) Q19.2(S) Q22.2(S) Q23.2(S) Q26.2(S) Q27.2(S) Q30.2(S) Q31.2(S) Q34.2(S) Q35.2(S) Q38.2(S) Q39.2(S) R100.2 R103.2 R106.2 R109.2 R112.2 R115.2 R118.2 R121.2 ; also sheet 1,2,3,4
N$10: D19.2(A) Q29.3(D)
N$11: D18.2(A) Q28.3(D)
N$17: Q27.3(D) Q28.1(G) R113.2
N$20: C33.- Q27.1(G) R112.1
N$31: D22.2(A) Q33.3(D)
N$77: D21.2(A) Q32.3(D)
N$78: Q31.3(D) Q32.1(G) R116.2
N$79: C34.- Q31.1(G) R115.1
N$80: D25.2(A) Q37.3(D)
N$81: D24.2(A) Q36.3(D)
N$82: Q35.3(D) Q36.1(G) R119.2
N$83: C35.- Q35.1(G) R118.1
N$84: D28.2(A) Q41.3(D)
N$85: D27.2(A) Q40.3(D)
N$86: Q39.3(D) Q40.1(G) R122.2
N$87: C36.- Q39.1(G) R121.1
N$88: D7.2(A) Q13.3(D)
N$89: D6.2(A) Q12.3(D)
N$90: Q11.3(D) Q12.1(G) R101.2
N$91: C29.- Q11.1(G) R100.1
N$100: D10.2(A) Q17.3(D)
N$108: D9.2(A) Q16.3(D)
N$109: Q15.3(D) Q16.1(G) R104.2
N$110: C30.- Q15.1(G) R103.1
N$111: D13.2(A) Q21.3(D)
N$112: D12.2(A) Q20.3(D)
N$113: Q19.3(D) Q20.1(G) R107.2
N$114: C31.- Q19.1(G) R106.1
N$115: D16.2(A) Q25.3(D)
N$116: D15.2(A) Q24.3(D)
N$117: Q23.3(D) Q24.1(G) R110.2
N$118: C32.- Q23.1(G) R109.1
VALVE1_CTRL: C33.+ Q26.1(G) ; also sheet 1
VALVE2_CTRL: C34.+ Q30.1(G) ; also sheet 1
VALVE3_CTRL: C35.+ Q34.1(G) ; also sheet 1
VALVE4_CTRL: C36.+ Q38.1(G) ; also sheet 1
VALVE5_CTRL: C29.+ Q10.1(G) ; also sheet 1
VALVE6_CTRL: C30.+ Q14.1(G) ; also sheet 1
VALVE7_CTRL: C31.+ Q18.1(G) ; also sheet 1
VALVE8_CTRL: C32.+ Q22.1(G) ; also sheet 1
VALVE_1_POWER: D18.1(C) D19.1(C) D20.1(C) ; also sheet 1
VALVE_2_POWER: D21.1(C) D22.1(C) D23.1(C) ; also sheet 1
VALVE_3_POWER: D24.1(C) D25.1(C) D26.1(C) ; also sheet 1
VALVE_4_POWER: D27.1(C) D28.1(C) D29.1(C) ; also sheet 1
VALVE_5_POWER: D6.1(C) D7.1(C) D8.1(C) ; also sheet 1
VALVE_6_POWER: D9.1(C) D10.1(C) D11.1(C) ; also sheet 1
VALVE_7_POWER: D12.1(C) D13.1(C) D14.1(C) ; also sheet 1
VALVE_8_POWER: D15.1(C) D16.1(C) D17.1(C) ; also sheet 1

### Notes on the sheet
- valve 5 | valve 6 | valve 7 | valve 8
- valve 1 | valve 2 | valve 3 | valve 4
- Valve Power Switch Sybsystem

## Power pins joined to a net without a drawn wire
+5V: IC5.14(P:VCC)
GND: IC5.7(P:GND)
NC: IC14.1(NC)

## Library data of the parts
C1 C3 C6-C8 C11 C14 C20-C22 C28 C60-C64 = TIMHOME:C0805
C2 C4 C5 C12 C18 C58 = discrete:ELC-5
C9 C10 C15-C17 C52 = pkmisc:POLCAP1210
C13 C27 = TIMHOME:C-BIG
C19 = discrete:CAPNP-5
C23 C24 = TIMHOME:CPOL
C25 C26 C37-C39 C45-C51 C53-C57 C59 = rcl:C-EU: CAPACITOR, European symbol
C29-C36 C40-C44 = albert:CPOL-US: POLARIZED CAPACITOR, American symbol
D1 = diode:1N5908: DIODE
D2 = diode:DIODE-: DIODE
D3 = diode:ES2D: DIODE
D4-D34 = albert:D-: DIODE
F1 R86-R128 = albert:R0805
IC1 = pkmisc:MAX1771
IC2 = pkmisc:LM2672
IC3 = pkmisc:ZXCT1009
IC4 IC7 IC9 IC10 U6 = TIMHOME:QUADOP
IC5 = 74xx-us:74*14: Hex schmitt trigger INVERTER
IC6 = TIMHOME:OPAMPSMD
IC8 = pkmisc:INA141
IC11 IC12 = pkmisc:DUALFET1
IC13 = analog-devices2:AD780
IC14 = pkmisc:ICL7660
IC15 IC16 = albert:INA141
IC17 = microchip:93-*: Serial EEPROM 512 x 8 bit/256 x 16 bit/1 K/4 K, 5.0 V, Microwire
J2 = TIMHOME:JUMP3
J3-J5 = TIMHOME:1X3
J6 = albert:IDC3
J10 = TIMHOME:1X5
L1 L3 = pkmisc:INDUCTOR1
L2 = pkmisc:INDUCTOR2
LED = TIMHOME:1X2
P1 P3 = albert:IDC60
P2 = con-berg:PN61729: BERG
Q1-Q4 = transistor-fet:IRF540: N-Channel Enhancement MOSFET (HEXFET); 100V; 28A; 0,077Ohm
Q5 = transistor-fet:IRF9530: P-Channel Enhancement MOSFET (HEXFET); -100V; -12A; 0,3Ohm
Q6 Q8 Q9 Q43 = pkmisc:MOSFETN
Q7 = transistor-npn:BCX20*: NPN Transistor
Q10 Q11 Q14 Q15 Q18 Q19 Q22 Q23 Q26 Q27 Q30 Q31 Q34 Q35 Q38 Q39 = albert:MOSFETN
Q12 Q13 Q16 Q17 Q20 Q21 Q24 Q25 Q28 Q29 Q32 Q33 Q36 Q37 Q40 Q41 = albert:MOSFETP
Q42 Q44 = pkmisc:MOSFETP
R0 R1-R20 R22-R29 R32 R35-R44 R46-R51 R54 R56-R80 R82 R83 R129-R131 = TIMHOME:R0805
R21 R30 R45 R81 = TIMHOME:R-1/4W
R31 = varistor:THERMISTOR: THERMISTOR
R33 R34 R52 R53 R55 = TIMHOME:TRIMPOT
R84 R85 = albert:POT
U1 = albert:PIC18F8720
U2 = albert:FT245BM
U3 = analog-devices2:AD7490: Analog Devices Fast 16 channel A/D
U4 = albert:AD7398
U5 = albert:MAX202
VR1 VR3 = pkmisc:TOKO_SOT23
VR2 = v-reg:TS5205: 150mA Low Noise LDO Voltage Regulator with Enable TSC [Taiwan Semiconductor Company, Ltd] Source: http://www.taiwansemi.com .. 5205_0409c.pdf
XT1 XT2 = crystal:CRYTAL: CRYSTAL

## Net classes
0 default: width 0.254 mm
2 +5V: width 0.203 mm, drill 0.508 mm, clearance 0.203 mm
